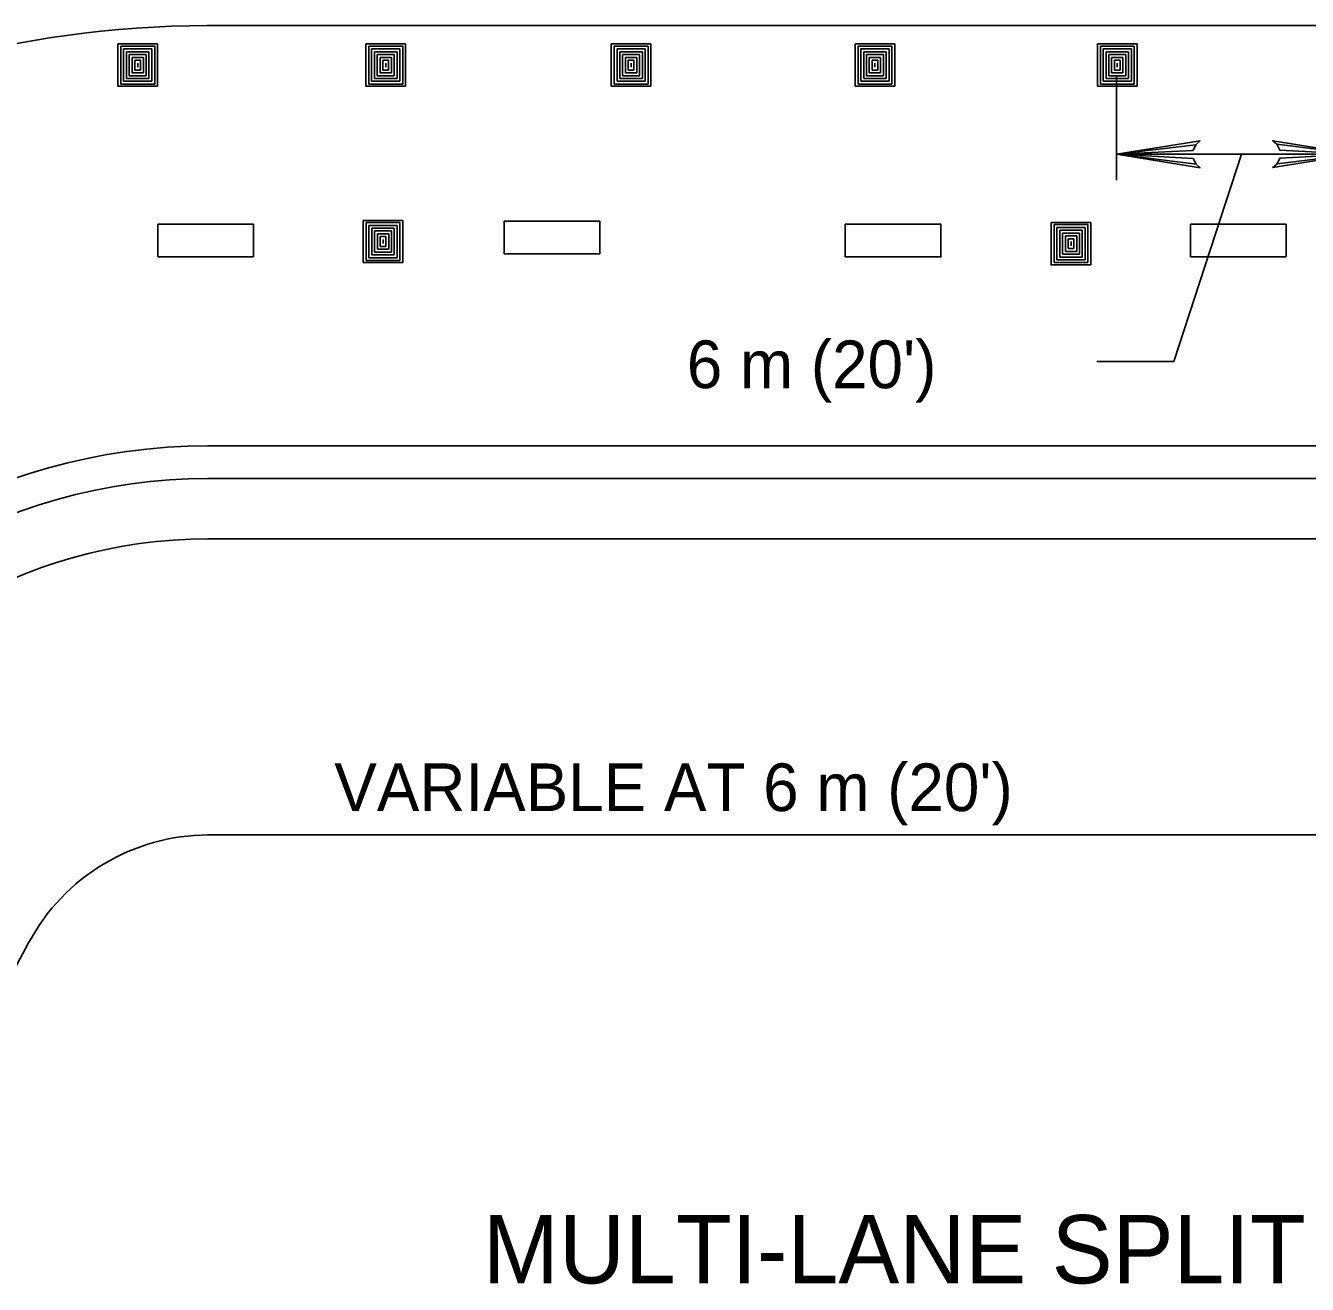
# Model space of a CAD drawing. Extents: x 639362 to 641108, y 298458 to 299646.
# Drawn here: x 639571.6 to 639652.3, y 299148 to 299227.2 of the extents above; entities that cross this region are included whole.
import ezdxf

# ---------------------------------------------------------------- set-up
doc = ezdxf.new("R2010")
doc.units = 0
doc.layers.add('2', color=7, linetype='Continuous')

msp = doc.modelspace()

# ---------------------------------------------------------------- linework, layer by layer
at = {"layer": '2'}
for p, q in [((639583.053, 299227.209), (639672.738, 299227.209)), ((639579.937, 299226.054), (639577.441, 299226.054)), ((639577.441, 299226.054), (639577.441, 299223.4)), ((639579.937, 299223.4), (639579.937, 299226.054)), ((639595.54, 299226.054), (639593.043, 299226.054)), ((639593.043, 299226.054), (639593.043, 299223.4)), ((639595.54, 299223.4), (639595.54, 299226.054)), ((639608.472, 299226.054), (639610.968, 299226.054)), ((639608.472, 299223.4), (639608.472, 299226.054)), ((639610.968, 299226.054), (639610.968, 299223.4)), ((639623.81, 299226.054), (639626.306, 299226.054)), ((639623.81, 299223.4), (639623.81, 299226.054)), ((639626.306, 299226.054), (639626.306, 299223.4)), ((639641.554, 299226.054), (639639.058, 299226.054)), ((639639.058, 299226.054), (639639.058, 299223.4)), ((639641.554, 299223.4), (639641.554, 299226.054)), ((639579.752, 299225.921), (639577.623, 299225.921)), ((639577.623, 299225.921), (639577.623, 299223.527)), ((639579.572, 299225.745), (639577.799, 299225.745)), ((639577.799, 299225.745), (639577.799, 299223.706)), ((639579.395, 299225.567), (639577.978, 299225.567)), ((639577.978, 299225.567), (639577.978, 299223.881)), ((639579.22, 299225.39), (639578.155, 299225.39)), ((639578.155, 299225.39), (639578.155, 299224.059)), ((639578.331, 299225.212), (639578.331, 299224.236)), ((639579.043, 299225.212), (639578.331, 299225.212)), ((639579.043, 299224.236), (639579.043, 299225.212)), ((639579.22, 299224.059), (639579.22, 299225.39)), ((639579.395, 299223.881), (639579.395, 299225.567)), ((639579.572, 299223.706), (639579.572, 299225.745)), ((639579.752, 299223.527), (639579.752, 299225.921)), ((639595.355, 299225.921), (639593.226, 299225.921)), ((639593.226, 299225.921), (639593.226, 299223.527)), ((639595.175, 299225.745), (639593.401, 299225.745)), ((639593.401, 299225.745), (639593.401, 299223.706)), ((639594.998, 299225.567), (639593.581, 299225.567)), ((639593.581, 299225.567), (639593.581, 299223.881)), ((639594.822, 299225.39), (639593.758, 299225.39)), ((639593.758, 299225.39), (639593.758, 299224.059)), ((639593.934, 299225.212), (639593.934, 299224.236)), ((639594.646, 299225.212), (639593.934, 299225.212)), ((639594.646, 299224.236), (639594.646, 299225.212)), ((639594.822, 299224.059), (639594.822, 299225.39)), ((639594.998, 299223.881), (639594.998, 299225.567)), ((639595.175, 299223.706), (639595.175, 299225.745)), ((639595.355, 299223.527), (639595.355, 299225.921)), ((639608.656, 299225.921), (639610.785, 299225.921)), ((639608.656, 299223.527), (639608.656, 299225.921)), ((639608.836, 299225.745), (639610.61, 299225.745)), ((639608.836, 299223.706), (639608.836, 299225.745)), ((639609.013, 299225.567), (639610.43, 299225.567)), ((639609.013, 299223.881), (639609.013, 299225.567)), ((639609.189, 299225.39), (639610.253, 299225.39)), ((639609.189, 299224.059), (639609.189, 299225.39)), ((639609.366, 299224.236), (639609.366, 299225.212)), ((639609.366, 299225.212), (639610.078, 299225.212)), ((639610.078, 299225.212), (639610.078, 299224.236)), ((639610.253, 299225.39), (639610.253, 299224.059)), ((639610.43, 299225.567), (639610.43, 299223.881)), ((639610.61, 299225.745), (639610.61, 299223.706)), ((639610.785, 299225.921), (639610.785, 299223.527)), ((639623.995, 299225.921), (639626.124, 299225.921)), ((639623.995, 299223.527), (639623.995, 299225.921)), ((639624.174, 299225.745), (639625.948, 299225.745)), ((639624.174, 299223.706), (639624.174, 299225.745)), ((639624.351, 299225.567), (639625.768, 299225.567)), ((639624.351, 299223.881), (639624.351, 299225.567)), ((639624.527, 299225.39), (639625.591, 299225.39)), ((639624.527, 299224.059), (639624.527, 299225.39)), ((639624.704, 299224.236), (639624.704, 299225.212)), ((639624.704, 299225.212), (639625.416, 299225.212)), ((639625.416, 299225.212), (639625.416, 299224.236)), ((639625.591, 299225.39), (639625.591, 299224.059)), ((639625.768, 299225.567), (639625.768, 299223.881)), ((639625.948, 299225.745), (639625.948, 299223.706)), ((639626.124, 299225.921), (639626.124, 299223.527)), ((639641.369, 299225.921), (639639.24, 299225.921)), ((639639.24, 299225.921), (639639.24, 299223.527)), ((639641.19, 299225.745), (639639.416, 299225.745)), ((639639.416, 299225.745), (639639.416, 299223.706)), ((639641.013, 299225.567), (639639.596, 299225.567)), ((639639.596, 299225.567), (639639.596, 299223.881)), ((639640.837, 299225.39), (639639.773, 299225.39)), ((639639.773, 299225.39), (639639.773, 299224.059)), ((639639.948, 299225.212), (639639.948, 299224.236)), ((639640.66, 299225.212), (639639.948, 299225.212)), ((639640.66, 299224.236), (639640.66, 299225.212)), ((639640.837, 299224.059), (639640.837, 299225.39)), ((639641.013, 299223.881), (639641.013, 299225.567)), ((639641.19, 299223.706), (639641.19, 299225.745)), ((639641.369, 299223.527), (639641.369, 299225.921)), ((639578.863, 299225.035), (639578.508, 299225.035)), ((639578.508, 299225.035), (639578.508, 299224.414)), ((639578.508, 299224.414), (639578.863, 299224.414)), ((639578.688, 299224.858), (639578.688, 299224.591)), ((639578.863, 299224.414), (639578.863, 299225.035)), ((639594.466, 299225.035), (639594.111, 299225.035)), ((639594.111, 299225.035), (639594.111, 299224.414)), ((639594.111, 299224.414), (639594.466, 299224.414)), ((639594.29, 299224.858), (639594.29, 299224.591)), ((639594.466, 299224.414), (639594.466, 299225.035)), ((639609.545, 299225.035), (639609.901, 299225.035)), ((639609.545, 299224.414), (639609.545, 299225.035)), ((639609.901, 299224.414), (639609.545, 299224.414)), ((639609.721, 299224.858), (639609.721, 299224.591)), ((639609.901, 299225.035), (639609.901, 299224.414)), ((639624.883, 299225.035), (639625.239, 299225.035)), ((639624.883, 299224.414), (639624.883, 299225.035)), ((639625.239, 299224.414), (639624.883, 299224.414)), ((639625.059, 299224.858), (639625.059, 299224.591)), ((639625.239, 299225.035), (639625.239, 299224.414)), ((639640.481, 299225.035), (639640.125, 299225.035)), ((639640.125, 299225.035), (639640.125, 299224.414)), ((639640.125, 299224.414), (639640.481, 299224.414)), ((639640.305, 299224.858), (639640.305, 299224.591)), ((639640.481, 299224.414), (639640.481, 299225.035)), ((639577.623, 299223.527), (639579.752, 299223.527)), ((639577.799, 299223.706), (639579.572, 299223.706)), ((639577.978, 299223.881), (639579.395, 299223.881)), ((639578.155, 299224.059), (639579.22, 299224.059)), ((639578.331, 299224.236), (639579.043, 299224.236)), ((639593.226, 299223.527), (639595.355, 299223.527)), ((639593.401, 299223.706), (639595.175, 299223.706)), ((639593.581, 299223.881), (639594.998, 299223.881)), ((639593.758, 299224.059), (639594.822, 299224.059)), ((639593.934, 299224.236), (639594.646, 299224.236)), ((639610.785, 299223.527), (639608.656, 299223.527)), ((639610.61, 299223.706), (639608.836, 299223.706)), ((639610.43, 299223.881), (639609.013, 299223.881)), ((639610.253, 299224.059), (639609.189, 299224.059)), ((639610.078, 299224.236), (639609.366, 299224.236)), ((639626.124, 299223.527), (639623.995, 299223.527)), ((639625.948, 299223.706), (639624.174, 299223.706)), ((639625.768, 299223.881), (639624.351, 299223.881)), ((639625.591, 299224.059), (639624.527, 299224.059)), ((639625.416, 299224.236), (639624.704, 299224.236)), ((639639.24, 299223.527), (639641.369, 299223.527)), ((639639.416, 299223.706), (639641.19, 299223.706)), ((639639.596, 299223.881), (639641.013, 299223.881)), ((639639.773, 299224.059), (639640.837, 299224.059)), ((639639.948, 299224.236), (639640.66, 299224.236)), ((639640.264, 299224.091), (639640.264, 299217.479)), ((639577.441, 299223.4), (639579.937, 299223.4)), ((639593.043, 299223.4), (639595.54, 299223.4)), ((639610.968, 299223.4), (639608.472, 299223.4)), ((639626.306, 299223.4), (639623.81, 299223.4)), ((639639.058, 299223.4), (639641.554, 299223.4)), ((639640.264, 299219.116), (639655.337, 299219.116)), ((639643.862, 299206.072), (639648.125, 299219.116)), ((639579.958, 299212.661), (639579.958, 299214.725)), ((639579.958, 299214.725), (639585.971, 299214.725)), ((639585.971, 299214.725), (639585.971, 299212.661)), ((639595.365, 299214.951), (639592.869, 299214.951)), ((639592.869, 299214.951), (639592.869, 299212.297)), ((639595.183, 299214.825), (639593.054, 299214.825)), ((639593.054, 299214.825), (639593.054, 299212.43)), ((639595.183, 299212.43), (639595.183, 299214.825)), ((639595.365, 299212.297), (639595.365, 299214.951)), ((639601.741, 299212.848), (639601.741, 299214.913)), ((639601.741, 299214.913), (639607.754, 299214.913)), ((639607.754, 299214.913), (639607.754, 299212.848)), ((639623.195, 299212.661), (639623.195, 299214.725)), ((639623.195, 299214.725), (639629.208, 299214.725)), ((639629.208, 299214.725), (639629.208, 299212.661)), ((639636.149, 299212.165), (639636.149, 299214.819)), ((639636.149, 299214.819), (639638.645, 299214.819)), ((639636.331, 299212.298), (639636.331, 299214.692)), ((639636.331, 299214.692), (639638.46, 299214.692)), ((639638.46, 299214.692), (639638.46, 299212.298)), ((639638.645, 299214.819), (639638.645, 299212.165)), ((639644.915, 299212.661), (639644.915, 299214.725)), ((639644.915, 299214.725), (639650.929, 299214.725)), ((639650.929, 299214.725), (639650.929, 299212.661)), ((639595.007, 299214.645), (639593.233, 299214.645)), ((639593.233, 299214.645), (639593.233, 299212.606)), ((639594.827, 299214.471), (639593.41, 299214.471)), ((639593.41, 299214.471), (639593.41, 299212.784)), ((639594.65, 299214.292), (639593.586, 299214.292)), ((639593.586, 299214.292), (639593.586, 299212.961)), ((639594.475, 299214.115), (639593.763, 299214.115)), ((639593.763, 299214.115), (639593.763, 299213.139)), ((639594.298, 299213.937), (639593.942, 299213.937)), ((639593.942, 299213.937), (639593.942, 299213.316)), ((639594.298, 299213.316), (639594.298, 299213.937)), ((639594.475, 299213.139), (639594.475, 299214.115)), ((639594.65, 299212.961), (639594.65, 299214.292)), ((639594.827, 299212.784), (639594.827, 299214.471)), ((639595.007, 299212.606), (639595.007, 299214.645)), ((639636.507, 299212.474), (639636.507, 299214.513)), ((639636.507, 299214.513), (639638.281, 299214.513)), ((639636.687, 299212.652), (639636.687, 299214.338)), ((639636.687, 299214.338), (639638.104, 299214.338)), ((639636.864, 299212.829), (639636.864, 299214.16)), ((639636.864, 299214.16), (639637.928, 299214.16)), ((639637.039, 299213.007), (639637.039, 299213.983)), ((639637.039, 299213.983), (639637.751, 299213.983)), ((639637.751, 299213.983), (639637.751, 299213.007)), ((639637.928, 299214.16), (639637.928, 299212.829)), ((639638.104, 299214.338), (639638.104, 299212.652)), ((639638.281, 299214.513), (639638.281, 299212.474)), ((639593.763, 299213.139), (639594.475, 299213.139)), ((639593.942, 299213.316), (639594.298, 299213.316)), ((639594.118, 299213.493), (639594.118, 299213.76)), ((639637.216, 299213.184), (639637.216, 299213.805)), ((639637.216, 299213.805), (639637.572, 299213.805)), ((639637.572, 299213.184), (639637.216, 299213.184)), ((639637.396, 299213.361), (639637.396, 299213.628)), ((639637.572, 299213.805), (639637.572, 299213.184)), ((639585.971, 299212.661), (639579.958, 299212.661)), ((639592.869, 299212.297), (639595.365, 299212.297)), ((639593.054, 299212.43), (639595.183, 299212.43)), ((639593.233, 299212.606), (639595.007, 299212.606)), ((639593.41, 299212.784), (639594.827, 299212.784)), ((639593.586, 299212.961), (639594.65, 299212.961)), ((639607.754, 299212.848), (639601.741, 299212.848)), ((639629.208, 299212.661), (639623.195, 299212.661)), ((639638.46, 299212.298), (639636.331, 299212.298)), ((639638.281, 299212.474), (639636.507, 299212.474)), ((639638.104, 299212.652), (639636.687, 299212.652)), ((639637.928, 299212.829), (639636.864, 299212.829)), ((639637.751, 299213.007), (639637.039, 299213.007)), ((639650.929, 299212.661), (639644.915, 299212.661)), ((639638.645, 299212.165), (639636.149, 299212.165)), ((639639.011, 299206.072), (639643.862, 299206.072)), ((639583.095, 299200.773), (639743.305, 299200.773)), ((639743.305, 299198.709), (639583.09, 299198.709)), ((639583.095, 299194.923), (639743.305, 299194.923)), ((639583.095, 299176.289), (639669.771, 299176.289)), ((639571.825, 299169.505), (639563.369, 299153.68))]:
    msp.add_line(p, q, dxfattribs=at)
for points in [[(639645.258, 299218.489), (639645.072, 299218.851), (639640.264, 299219.116), (639645.258, 299218.489), (639645.514, 299218.27), (639640.264, 299219.116), (639645.068, 299219.354), (639645.244, 299219.712), (639640.264, 299219.116), (639645.514, 299219.951), (639645.244, 299219.712)], [(639650.342, 299219.743), (639650.528, 299219.382), (639655.337, 299219.116), (639650.342, 299219.743), (639650.086, 299219.962), (639655.337, 299219.116), (639650.532, 299218.879), (639650.357, 299218.521), (639655.337, 299219.116), (639650.086, 299218.282), (639650.357, 299218.521)]]:
    msp.add_lwpolyline(points, dxfattribs=at)
for centre, radius in [((639583.134, 299162.428), 64.782), ((639583.142, 299163.458), 37.315), ((639583.142, 299163.458), 35.251), ((639583.142, 299163.458), 31.465), ((639583.142, 299163.458), 12.831)]:
    msp.add_arc(centre, radius, 90.07158, 151.88213, dxfattribs=at)

# ---------------------------------------------------------------- texts
for s, height, p in [("6 m (20')", 3, (639613.226, 299204.4)), ("VARIABLE AT 6 m (20')", 3, (639591.051, 299177.79)), ('MULTI-LANE SPLIT', 4.3, (639600.392, 299148.077))]:
    msp.add_text(s, height=height, dxfattribs=at).set_placement(p)

doc.saveas('drawing.dxf')
